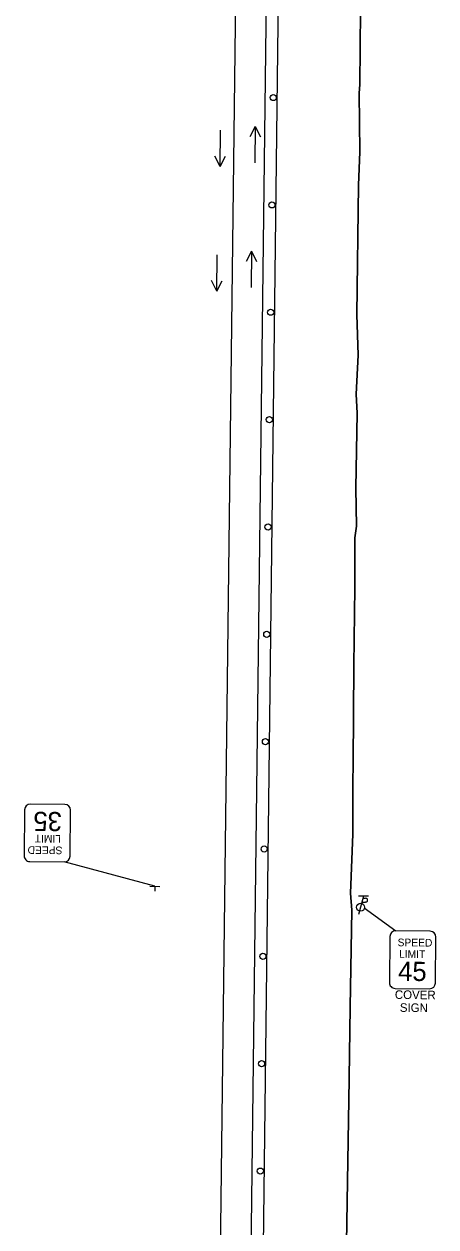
# Model space of a CAD drawing. Extents: x 1650647 to 1653016, y 602856 to 611467.
# Drawn here: x 1650661.1 to 1650795.3, y 607707.9 to 608100.1 of the extents above; entities that cross this region are included whole.
import ezdxf

# ---------------------------------------------------------------- set-up
doc = ezdxf.new("R2010")
doc.units = 0
for name, color, linetype in [('CM_Corridor_Design', 7, 'Continuous'), ('DT_X_Break_Line', 7, 'Continuous'), ('DT_X_Contour_Major', 7, 'Continuous'), ('MD_P_Drive_MatchLine', 7, 'Continuous'), ('MD_P_Intersection_MatchLine', 7, 'Continuous'), ('PF_X_Ground_Line', 7, 'Continuous'), ('PV_P_EOP', 7, 'Continuous'), ('PV_X_EOP', 7, 'Continuous'), ('UT_X_Gas', 7, 'Continuous')]:
    doc.layers.add(name, color=color, linetype=linetype)

msp = doc.modelspace()

# ---------------------------------------------------------------- linework, layer by layer
at = {"layer": 'CM_Corridor_Design'}
for p, q in [((1650724.96, 608053.61), (1650725.09, 608065.47)), ((1650736.37, 608066.63), (1650734.61, 608063.28)), ((1650736.37, 608066.63), (1650736.24, 608054.77)), ((1650736.37, 608066.63), (1650738.06, 608063.24)), ((1650724.96, 608053.61), (1650723.27, 608057.01)), ((1650724.96, 608053.61), (1650726.72, 608056.97)), ((1650723.82, 608013.01), (1650723.95, 608024.87)), ((1650735.16, 608026.03), (1650733.4, 608022.68)), ((1650735.16, 608026.03), (1650735.03, 608014.17)), ((1650735.16, 608026.03), (1650736.84, 608022.64)), ((1650723.82, 608013.01), (1650722.13, 608016.4)), ((1650723.82, 608013.01), (1650725.58, 608016.36))]:
    msp.add_line(p, q, dxfattribs=at)
at = {"layer": 'DT_X_Break_Line'}
for centre in [(1650742.25, 608076.09), (1650741.81, 608041.09), (1650741.4, 608006.1), (1650740.98, 607971.1), (1650740.56, 607936.09), (1650740.13, 607901.11), (1650739.71, 607866.11), (1650739.29, 607831.11), (1650738.87, 607796.11), (1650738.44, 607761.12), (1650738.02, 607726.12)]:
    msp.add_circle(centre, 1, dxfattribs=at)
at = {"layer": 'DT_X_Contour_Major'}
for points in [[(1650734.65, 607330.15), (1650750.73, 608671.04)], [(1650766.08, 607702.78), (1650766.89, 607749.39), (1650766.84, 607748.9), (1650767.26, 607779.54), (1650767.81, 607811.15), (1650767.41, 607816.67), (1650768.2, 607835.98), (1650768.13, 607852.59), (1650768.26, 607859.12), (1650768.46, 607890.91), (1650768.87, 607916.33), (1650768.85, 607932.56), (1650769.34, 607936.38), (1650769.15, 607948.75), (1650769.62, 607973.21), (1650769.29, 607979.37), (1650769.87, 607992.16), (1650769.5, 608005.41), (1650770.03, 608047.52), (1650770.42, 608058.36), (1650770.29, 608077.5), (1650770.5, 608080.35), (1650770.48, 608080.28), (1650770.71, 608104.53)], [(1650770.71, 608104.53), (1650770.48, 608080.28), (1650770.5, 608080.35), (1650770.29, 608077.5), (1650770.42, 608058.36), (1650770.03, 608047.52), (1650769.5, 608005.41), (1650769.87, 607992.16), (1650769.29, 607979.37), (1650769.62, 607973.21), (1650769.15, 607948.75), (1650769.34, 607936.38), (1650768.85, 607932.56), (1650768.87, 607916.33), (1650768.46, 607890.91), (1650768.26, 607859.12), (1650768.13, 607852.59), (1650768.2, 607835.98), (1650767.41, 607816.67), (1650767.81, 607811.15), (1650767.26, 607779.54), (1650766.84, 607748.9), (1650766.89, 607749.39), (1650766.08, 607702.78)]]:
    msp.add_lwpolyline(points, dxfattribs=at)
at = {"layer": 'MD_P_Drive_MatchLine'}
for p, q in [((1650703.66, 607818.97), (1650674.16, 607826.91)), ((1650771.91, 607811.92), (1650782.15, 607804.43))]:
    msp.add_line(p, q, dxfattribs=at)
at = {"layer": 'MD_P_Intersection_MatchLine'}
for p, q in [((1650771.67, 607815.72), (1650770.06, 607809.72)), ((1650773.27, 607815.72), (1650770.07, 607815.72)), ((1650771.51, 607815.12), (1650772.36, 607815.12)), ((1650771.17, 607813.84), (1650772.36, 607813.84))]:
    msp.add_line(p, q, dxfattribs=at)
msp.add_circle((1650770.7, 607812.12), 1.3, dxfattribs=at)
msp.add_arc((1650772.37, 607814.48), 0.638, 268.8767, 91.1233, dxfattribs=at)
at = {"layer": 'PF_X_Ground_Line'}
for points in [[(1650674.37, 607845.66), (1650663.12, 607845.78)], [(1650661.22, 607843.92), (1650661.06, 607828.93)], [(1650676.06, 607828.76), (1650676.22, 607843.76)], [(1650662.91, 607827.03), (1650674.16, 607826.91)], [(1650780.26, 607802.58), (1650780.09, 607787.58)], [(1650793.4, 607804.31), (1650782.15, 607804.43)], [(1650795.09, 607787.41), (1650795.26, 607802.41)], [(1650781.95, 607785.68), (1650793.2, 607785.56)]]:
    msp.add_lwpolyline(points, dxfattribs=at)
for centre, radius, start, end in [((1650663.1, 607843.9), 1.87, 89.3709, 179.3709), ((1650674.35, 607843.78), 1.87, 359.3709, 89.3709), ((1650662.94, 607828.9), 1.87, 179.3709, 269.3709), ((1650674.18, 607828.78), 1.87, 269.3709, 359.3709), ((1650782.13, 607802.56), 1.88, 89.3709, 179.3709), ((1650793.38, 607802.43), 1.88, 359.3709, 89.3709), ((1650781.97, 607787.56), 1.88, 179.3709, 269.3709), ((1650793.22, 607787.44), 1.88, 269.3709, 359.3709)]:
    msp.add_arc(centre, radius, start, end, dxfattribs=at)
at = {"layer": 'PV_P_EOP'}
msp.add_line((1650730.58, 607324.51), (1650746.85, 608670.57), dxfattribs=at)
at = {"layer": 'PV_X_EOP'}
msp.add_line((1650720.58, 607324.64), (1650736.86, 608671.61), dxfattribs=at)
at = {"layer": 'UT_X_Gas'}
for p, q in [((1650702.06, 607819.01), (1650705.26, 607818.93)), ((1650703.66, 607818.97), (1650703.62, 607817.37)), ((1650703.66, 607818.97), (1650703.66, 607818.97))]:
    msp.add_line(p, q, dxfattribs=at)

# ---------------------------------------------------------------- texts
at = {"layer": 'CM_Corridor_Design'}
for s, p in [('COVER', (1650781.86, 607782.26)), ('SIGN', (1650783.48, 607778.04))]:
    msp.add_text(s, height=2.8, rotation=359.3709, dxfattribs=at).set_placement(p)
at = {"layer": 'PF_X_Ground_Line'}
for s, height, rotation, p in [('35', 6.25, 179.3709, (1650673.42, 607843.17)), ('LIMIT', 2.5, 179.3709, (1650673.09, 607835.67)), ('SPEED', 2.5, 179.3709, (1650673.56, 607831.91)), ('SPEED', 2.5, 359.3709, (1650782.75, 607799.43)), ('LIMIT', 2.5, 359.3709, (1650783.23, 607795.67)), ('45', 6.25, 359.3709, (1650782.9, 607788.17))]:
    msp.add_text(s, height=height, rotation=rotation, dxfattribs=at).set_placement(p)

doc.saveas('drawing.dxf')
